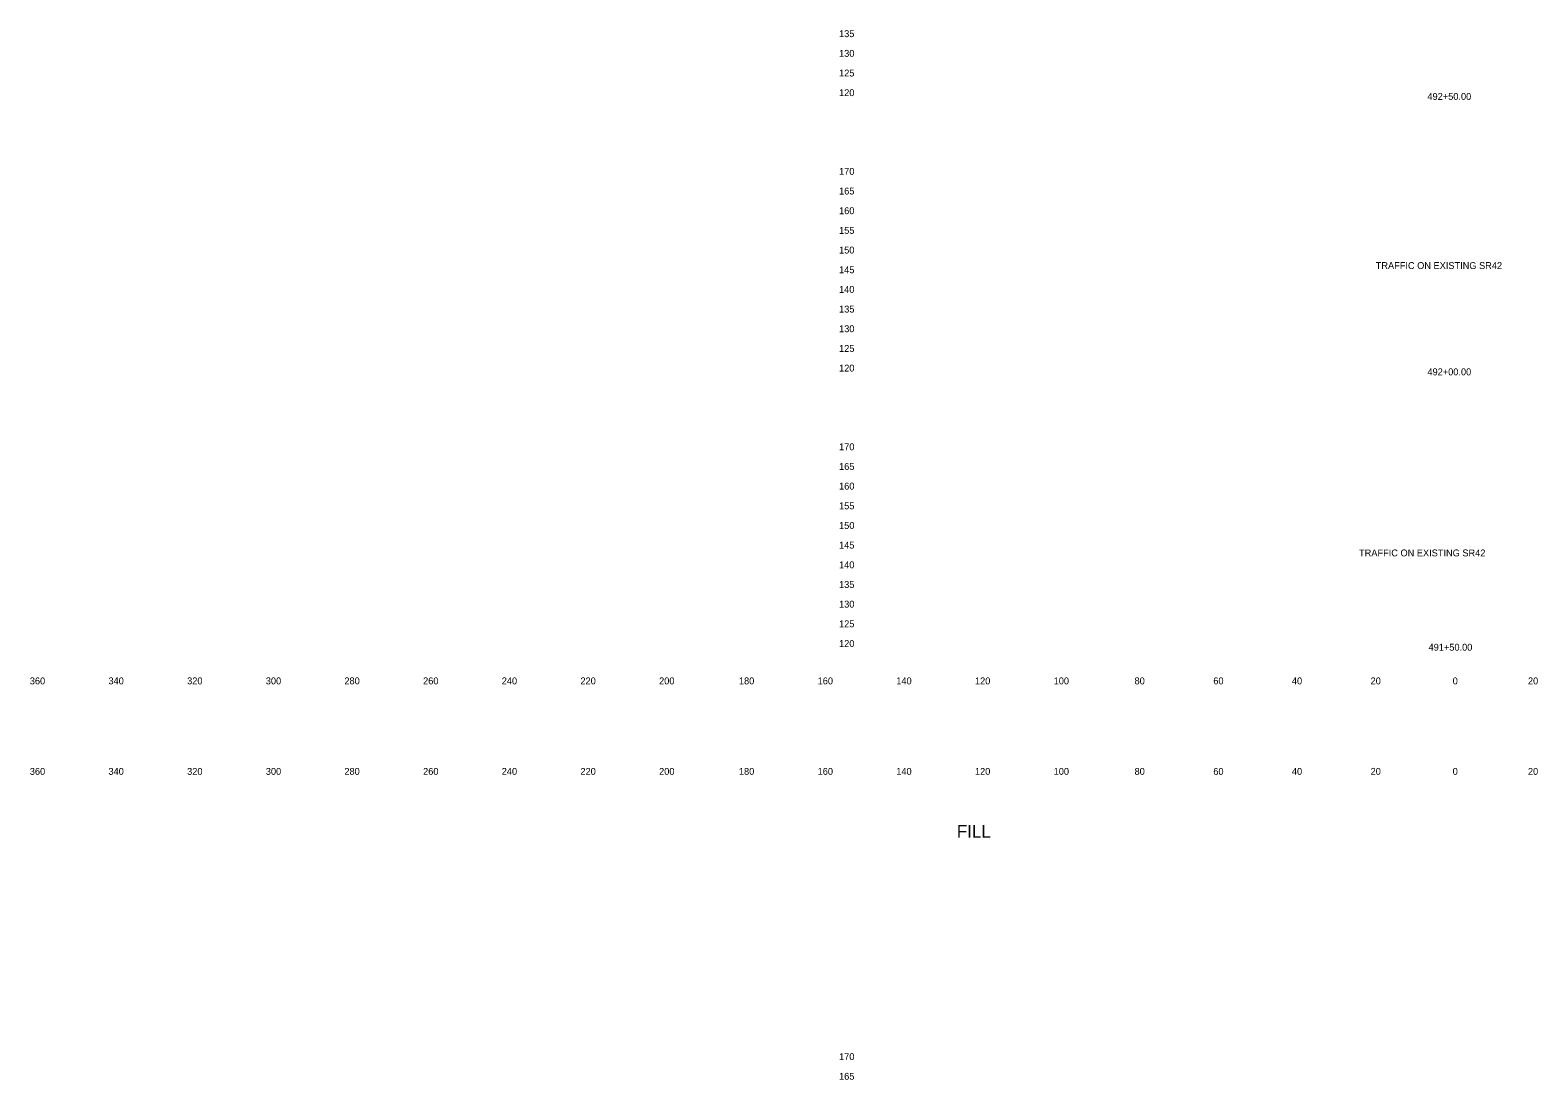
# Model space of a CAD drawing. Extents: x 21281 to 22024, y 6472 to 15198.
# Drawn here: x 21280.5 to 21663.8, y 14654.8 to 14921.6 of the extents above; entities that cross this region are included whole.
import ezdxf

# ---------------------------------------------------------------- set-up
doc = ezdxf.new("R2010")
doc.units = 0
for name, color, linetype in [('XS_SHEET_LABELS_ELEVATION', 7, 'Continuous'), ('XS_SHEET_LABELS_OFFSET', 7, 'Continuous'), ('XS_SHEET_LABELS_STATION', 7, 'Continuous')]:
    doc.layers.add(name, color=color, linetype=linetype)

msp = doc.modelspace()

# ---------------------------------------------------------------- texts
at = {"layer": 'XS_SHEET_LABELS_ELEVATION'}
for s, p in [('  135  ', (21484.84, 14919.84)), ('  130  ', (21484.84, 14914.84)), ('  125  ', (21484.84, 14909.84)), ('  120  ', (21484.84, 14904.84)), ('  170  ', (21484.84, 14884.84)), ('  165  ', (21484.84, 14879.84)), ('  160  ', (21484.84, 14874.84)), ('  155  ', (21484.84, 14869.84)), ('  150  ', (21484.84, 14864.84)), ('  145  ', (21484.84, 14859.84)), ('  140  ', (21484.84, 14854.84)), ('  135  ', (21484.84, 14849.84)), ('  130  ', (21484.84, 14844.84)), ('  125  ', (21484.84, 14839.84)), ('  120  ', (21484.84, 14834.84)), ('  170  ', (21484.84, 14814.84)), ('  165  ', (21484.84, 14809.84)), ('  160  ', (21484.84, 14804.84)), ('  155  ', (21484.84, 14799.84)), ('  150  ', (21484.84, 14794.84)), ('  145  ', (21484.84, 14789.84)), ('  140  ', (21484.84, 14784.84)), ('  135  ', (21484.84, 14779.84)), ('  130  ', (21484.84, 14774.84)), ('  125  ', (21484.84, 14769.84)), ('  120  ', (21484.84, 14764.84)), ('  170  ', (21484.84, 14659.84)), ('  165  ', (21484.84, 14654.84))]:
    msp.add_text(s, height=1.75, dxfattribs=at).set_placement(p)
at = {"layer": 'XS_SHEET_LABELS_OFFSET'}
for s, height, p in [('  360  ', 1.75, (21279.14, 14755.34)), ('  340  ', 1.75, (21299.13, 14755.34)), ('  320  ', 1.75, (21319.13, 14755.34)), ('  300  ', 1.75, (21339.13, 14755.34)), ('  280  ', 1.75, (21359.1, 14755.34)), ('  260  ', 1.75, (21379.11, 14755.34)), ('  240  ', 1.75, (21399.1, 14755.34)), ('  220  ', 1.75, (21419.1, 14755.34)), ('  200  ', 1.75, (21439.1, 14755.34)), ('  180  ', 1.75, (21459.39, 14755.34)), ('  160  ', 1.75, (21479.4, 14755.34)), ('  140  ', 1.75, (21499.39, 14755.34)), ('  120  ', 1.75, (21519.39, 14755.34)), ('  100  ', 1.75, (21539.39, 14755.34)), ('  80  ', 1.75, (21559.95, 14755.34)), ('  60  ', 1.75, (21579.97, 14755.34)), ('  40  ', 1.75, (21599.95, 14755.34)), ('  20  ', 1.75, (21619.95, 14755.34)), ('  0  ', 1.75, (21640.81, 14755.34)), ('  0  ', 1.75, (21640.81, 14755.34)), ('  20  ', 1.75, (21659.95, 14755.34)), ('  360  ', 1.75, (21279.14, 14732.34)), ('  340  ', 1.75, (21299.13, 14732.34)), ('  320  ', 1.75, (21319.13, 14732.34)), ('  300  ', 1.75, (21339.13, 14732.34)), ('  280  ', 1.75, (21359.1, 14732.34)), ('  260  ', 1.75, (21379.11, 14732.34)), ('  240  ', 1.75, (21399.1, 14732.34)), ('  220  ', 1.75, (21419.1, 14732.34)), ('  200  ', 1.75, (21439.1, 14732.34)), ('  180  ', 1.75, (21459.39, 14732.34)), ('  160  ', 1.75, (21479.4, 14732.34)), ('  140  ', 1.75, (21499.39, 14732.34)), ('  120  ', 1.75, (21519.39, 14732.34)), ('  100  ', 1.75, (21539.39, 14732.34)), ('  80  ', 1.75, (21559.95, 14732.34)), ('  60  ', 1.75, (21579.97, 14732.34)), ('  40  ', 1.75, (21599.95, 14732.34)), ('  20  ', 1.75, (21619.95, 14732.34)), ('  0  ', 1.75, (21640.81, 14732.34)), ('  0  ', 1.75, (21640.81, 14732.34)), ('  20  ', 1.75, (21659.95, 14732.34)), ('FILL', 3.222, (21516.08, 14716.39))]:
    msp.add_text(s, height=height, dxfattribs=at).set_placement(p)
at = {"layer": 'XS_SHEET_LABELS_STATION'}
for s, p in [('  492+50.00  ', (21634.4, 14903.89)), ('TRAFFIC ON EXISTING SR42', (21622.56, 14860.9)), ('  492+00.00  ', (21634.4, 14833.89)), ('TRAFFIC ON EXISTING SR42', (21618.32, 14787.86)), ('  491+50.00  ', (21634.69, 14763.89))]:
    msp.add_text(s, height=1.75, dxfattribs=at).set_placement(p)

doc.saveas('drawing.dxf')
